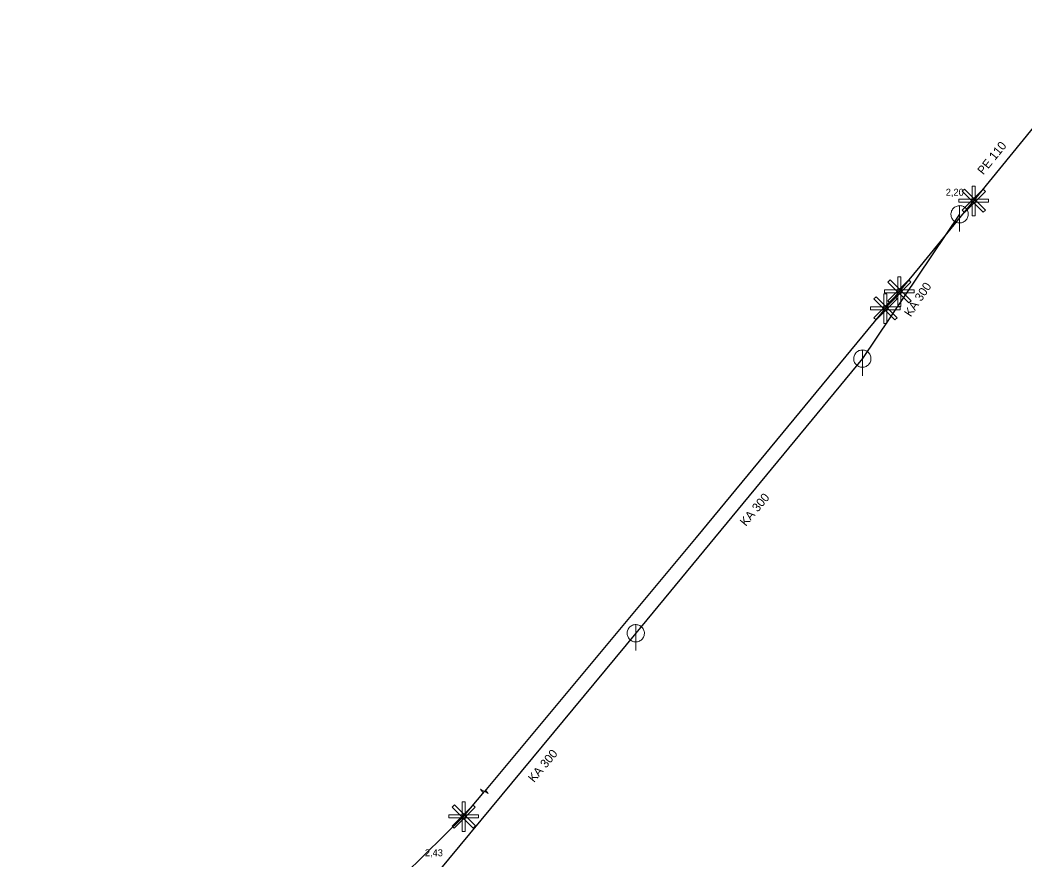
# Model space of a CAD drawing. Extents: x -809028 to -807737, y -990545 to -989489.
# Drawn here: x -808791.3 to -808675, y -989928.5 to -989831.3 of the extents above; entities that cross this region are included whole.
import ezdxf

# ---------------------------------------------------------------- set-up
doc = ezdxf.new("R2010")
doc.units = 0
doc.header["$LTSCALE"] = 0.32
for name, color, linetype, lineweight in [('1', 7, 'Continuous', 13), ('12', 7, 'Continuous', 13), ('14', 7, 'Continuous', 25), ('17', 7, 'Continuous', 25), ('22', 7, 'Continuous', 13), ('47', 7, 'Continuous', 13)]:
    doc.layers.add(name, color=color, linetype=linetype, lineweight=lineweight)

msp = doc.modelspace()

# ---------------------------------------------------------------- linework, layer by layer
at = {"layer": '12'}
for points in [[(-808679.839, -989850.865), (-808679.591, -989851.113), (-808682.02, -989853.542), (-808682.267, -989853.294)], [(-808682.258, -989851.104), (-808682.011, -989850.856), (-808679.582, -989853.285), (-808679.829, -989853.533)], [(-808681.105, -989850.501), (-808680.755, -989850.501), (-808680.755, -989853.936), (-808681.105, -989853.936)], [(-808679.221, -989852.01), (-808679.221, -989852.36), (-808682.656, -989852.36), (-808682.656, -989852.01)], [(-808688.446, -989861.371), (-808688.198, -989861.619), (-808690.627, -989864.048), (-808690.874, -989863.8)], [(-808690.865, -989861.61), (-808690.618, -989861.362), (-808688.189, -989863.791), (-808688.436, -989864.039)], [(-808689.712, -989861.007), (-808689.362, -989861.007), (-808689.362, -989864.442), (-808689.712, -989864.442)], [(-808687.828, -989862.516), (-808687.828, -989862.866), (-808691.263, -989862.866), (-808691.263, -989862.516)], [(-808690.062, -989863.329), (-808689.814, -989863.577), (-808692.243, -989866.006), (-808692.49, -989865.758)], [(-808692.481, -989863.568), (-808692.234, -989863.32), (-808689.805, -989865.749), (-808690.052, -989865.997)], [(-808691.328, -989862.965), (-808690.978, -989862.965), (-808690.978, -989866.4), (-808691.328, -989866.4)], [(-808689.444, -989864.474), (-808689.444, -989864.824), (-808692.879, -989864.824), (-808692.879, -989864.474)], [(-808740.141, -989921.814), (-808739.791, -989921.814), (-808739.791, -989925.249), (-808740.141, -989925.249)], [(-808738.875, -989922.178), (-808738.627, -989922.426), (-808741.056, -989924.855), (-808741.303, -989924.607)], [(-808741.294, -989922.417), (-808741.047, -989922.169), (-808738.618, -989924.598), (-808738.865, -989924.846)], [(-808738.257, -989923.323), (-808738.257, -989923.673), (-808741.692, -989923.673), (-808741.692, -989923.323)]]:
    msp.add_lwpolyline(points, close=True, dxfattribs=at)
at = {"layer": '14'}
for p, q in [((-808682.571, -989853.768), (-808693.828, -989870.481)), ((-808693.828, -989870.481), (-808720.057, -989902.284)), ((-808720.057, -989902.284), (-808742.862, -989929.815))]:
    msp.add_line(p, q, dxfattribs=at)
at = {"layer": '17'}
for points in [[(-808664.399, -989831.279), (-808667.17, -989835.318), (-808687.175, -989859.809), (-808713.068, -989891.184), (-808737.574, -989920.606)], [(-808791.319, -989951.829), (-808789.127, -989950.927), (-808781.745, -989948.142), (-808770.64, -989943.239), (-808765.44, -989941.024), (-808762.77, -989939.84), (-808754.828, -989936.5), (-808746.842, -989930.234), (-808739.984, -989923.5), (-808737.574, -989920.606)]]:
    msp.add_lwpolyline(points, dxfattribs=at)
at = {"layer": '22'}
for p, q in [((-808682.571, -989855.768), (-808682.57, -989852.768)), ((-808693.828, -989872.481), (-808693.827, -989869.481)), ((-808720.057, -989904.284), (-808720.056, -989901.284))]:
    msp.add_line(p, q, dxfattribs=at)
for points in [[(-808681.571, -989853.768), (-808681.576, -989853.659), (-808681.594, -989853.551), (-808681.624, -989853.445), (-808681.664, -989853.344), (-808681.716, -989853.247), (-808681.778, -989853.157), (-808681.85, -989853.074), (-808681.93, -989853), (-808682.018, -989852.934), (-808682.112, -989852.879), (-808682.212, -989852.834), (-808682.317, -989852.801), (-808682.424, -989852.779), (-808682.533, -989852.769), (-808682.643, -989852.771), (-808682.751, -989852.785), (-808682.858, -989852.81), (-808682.961, -989852.847), (-808683.059, -989852.896), (-808683.151, -989852.954), (-808683.237, -989853.023), (-808683.314, -989853.1), (-808683.383, -989853.186), (-808683.442, -989853.278), (-808683.49, -989853.376), (-808683.527, -989853.479), (-808683.553, -989853.586), (-808683.567, -989853.694), (-808683.57, -989853.804), (-808683.56, -989853.913), (-808683.539, -989854.02), (-808683.505, -989854.124), (-808683.461, -989854.224), (-808683.406, -989854.319), (-808683.34, -989854.407), (-808683.266, -989854.487), (-808683.183, -989854.559), (-808683.093, -989854.621), (-808682.997, -989854.673), (-808682.895, -989854.714), (-808682.79, -989854.744), (-808682.682, -989854.762), (-808682.572, -989854.768), (-808682.463, -989854.762), (-808682.355, -989854.744), (-808682.25, -989854.715), (-808682.148, -989854.674), (-808682.051, -989854.622), (-808681.961, -989854.56), (-808681.878, -989854.489), (-808681.803, -989854.409), (-808681.738, -989854.321), (-808681.682, -989854.227), (-808681.638, -989854.127), (-808681.604, -989854.023), (-808681.582, -989853.915), (-808681.572, -989853.806)], [(-808692.828, -989870.481), (-808692.833, -989870.372), (-808692.851, -989870.264), (-808692.881, -989870.158), (-808692.921, -989870.057), (-808692.973, -989869.96), (-808693.035, -989869.87), (-808693.107, -989869.787), (-808693.187, -989869.713), (-808693.275, -989869.647), (-808693.369, -989869.592), (-808693.469, -989869.547), (-808693.574, -989869.514), (-808693.681, -989869.492), (-808693.79, -989869.482), (-808693.9, -989869.484), (-808694.008, -989869.498), (-808694.115, -989869.523), (-808694.218, -989869.56), (-808694.316, -989869.609), (-808694.408, -989869.667), (-808694.494, -989869.736), (-808694.571, -989869.813), (-808694.64, -989869.899), (-808694.699, -989869.991), (-808694.747, -989870.089), (-808694.784, -989870.192), (-808694.81, -989870.299), (-808694.824, -989870.407), (-808694.827, -989870.517), (-808694.817, -989870.626), (-808694.796, -989870.733), (-808694.762, -989870.837), (-808694.718, -989870.937), (-808694.663, -989871.032), (-808694.597, -989871.12), (-808694.523, -989871.2), (-808694.44, -989871.272), (-808694.35, -989871.334), (-808694.254, -989871.386), (-808694.152, -989871.427), (-808694.047, -989871.457), (-808693.939, -989871.475), (-808693.829, -989871.481), (-808693.72, -989871.475), (-808693.612, -989871.457), (-808693.507, -989871.428), (-808693.405, -989871.387), (-808693.308, -989871.335), (-808693.218, -989871.273), (-808693.135, -989871.202), (-808693.06, -989871.122), (-808692.995, -989871.034), (-808692.939, -989870.94), (-808692.895, -989870.84), (-808692.861, -989870.736), (-808692.839, -989870.628), (-808692.829, -989870.519)], [(-808719.057, -989902.284), (-808719.062, -989902.175), (-808719.08, -989902.067), (-808719.11, -989901.961), (-808719.15, -989901.86), (-808719.202, -989901.763), (-808719.264, -989901.673), (-808719.336, -989901.59), (-808719.416, -989901.516), (-808719.504, -989901.45), (-808719.598, -989901.395), (-808719.698, -989901.35), (-808719.803, -989901.317), (-808719.91, -989901.295), (-808720.019, -989901.285), (-808720.129, -989901.287), (-808720.237, -989901.301), (-808720.344, -989901.326), (-808720.447, -989901.363), (-808720.545, -989901.412), (-808720.637, -989901.47), (-808720.723, -989901.539), (-808720.8, -989901.616), (-808720.869, -989901.702), (-808720.928, -989901.794), (-808720.976, -989901.892), (-808721.013, -989901.995), (-808721.039, -989902.102), (-808721.053, -989902.21), (-808721.056, -989902.32), (-808721.046, -989902.429), (-808721.025, -989902.536), (-808720.991, -989902.64), (-808720.947, -989902.74), (-808720.892, -989902.835), (-808720.826, -989902.923), (-808720.752, -989903.003), (-808720.669, -989903.075), (-808720.579, -989903.137), (-808720.483, -989903.189), (-808720.381, -989903.23), (-808720.276, -989903.26), (-808720.168, -989903.278), (-808720.058, -989903.284), (-808719.949, -989903.278), (-808719.841, -989903.26), (-808719.736, -989903.231), (-808719.634, -989903.19), (-808719.537, -989903.138), (-808719.447, -989903.076), (-808719.364, -989903.005), (-808719.289, -989902.925), (-808719.224, -989902.837), (-808719.168, -989902.743), (-808719.124, -989902.643), (-808719.09, -989902.539), (-808719.068, -989902.431), (-808719.058, -989902.322)]]:
    msp.add_lwpolyline(points, close=True, dxfattribs=at)
at = {"layer": '47'}
msp.add_line((-808738.019, -989920.357), (-808737.703, -989920.759), dxfattribs=at)
msp.add_lwpolyline([(-808738.019, -989920.357), (-808737.128, -989920.854), (-808737.444, -989920.452)], dxfattribs=at)

# ---------------------------------------------------------------- texts
at = {"layer": '1'}
for s, rotation, p in [('PE 110', 51, (-808679.832, -989849.263)), ('KA 300', 56, (-808688.229, -989865.721)), ('KA 300', 50, (-808707.32, -989889.96)), ('KA 300', 50, (-808731.844, -989919.626))]:
    msp.add_text(s, height=1, rotation=rotation, dxfattribs=at).set_placement(p)
for s, p in [('2,20', (-808684.171, -989851.615)), ('2,43', (-808744.461, -989928.103))]:
    msp.add_text(s, height=0.8, dxfattribs=at).set_placement(p)

doc.saveas('drawing.dxf')
